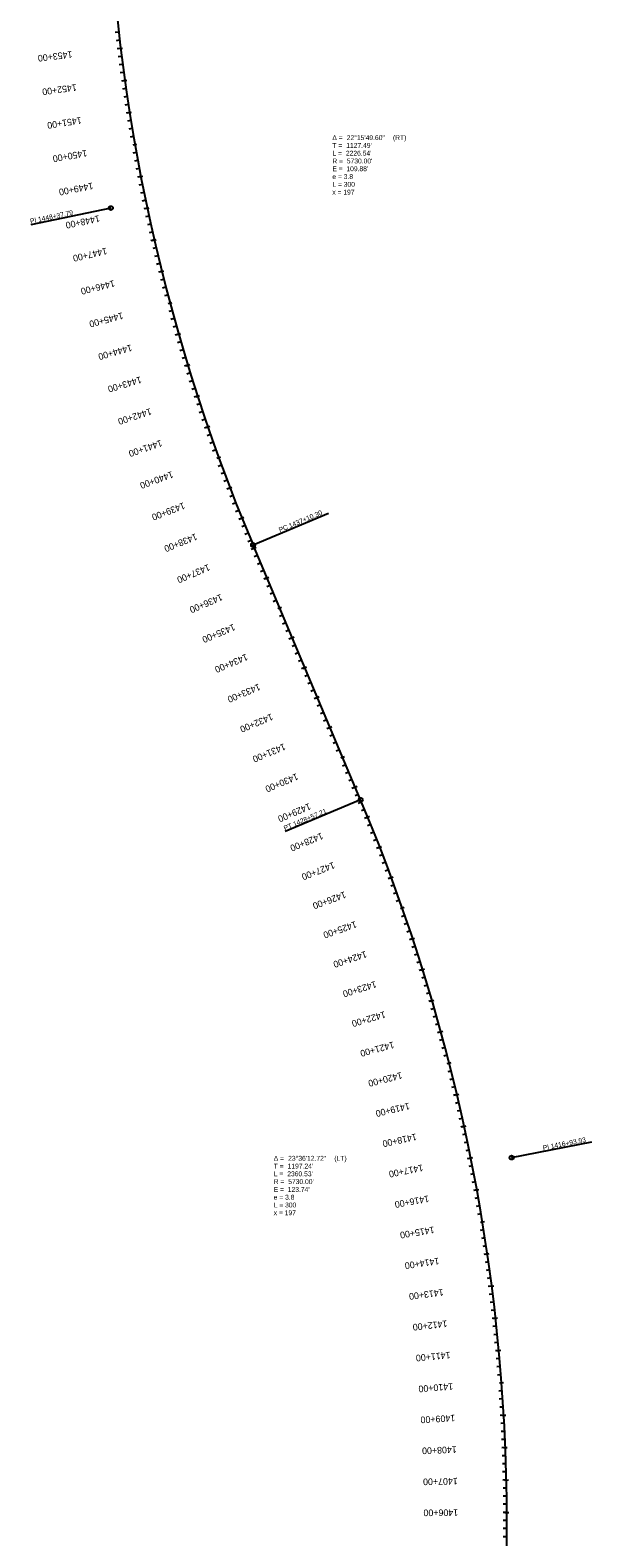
# Model space of a CAD drawing. Extents: x 20505176 to 20507193, y 7960287 to 7982631.
# Drawn here: x 20505239 to 20506971, y 7973323 to 7977971 of the extents above; entities that cross this region are included whole.
import ezdxf

# ---------------------------------------------------------------- set-up
doc = ezdxf.new("R2010")
doc.units = 0
for name, color, linetype in [('Alignment', 7, 'Continuous'), ('TextAlignment', 7, 'Continuous'), ('TextAlignmentLrg', 7, 'Continuous'), ('TextAlignmentSml', 7, 'Continuous')]:
    doc.layers.add(name, color=color, linetype=linetype)

msp = doc.modelspace()

# ---------------------------------------------------------------- linework, layer by layer
at = {"layer": 'Alignment'}
msp.add_line((20506257.8, 7975598.2), (20505926.1, 7976384.1), dxfattribs=at)
for centre, start, end in [((20511205.4, 7978611.7), 180.61343, 202.8772), ((20500978.6, 7973370.4), 359.27591, 22.87944)]:
    msp.add_arc(centre, 5730, start, end, dxfattribs=at)
at = {"layer": 'TextAlignment'}
for p, q in [((20505487.8, 7977422.9), (20505241.1, 7977371.6)), ((20505241.1, 7977371.6), (20505241.1, 7977371.6)), ((20505926.1, 7976384.1), (20506158.3, 7976482.1)), ((20506158.3, 7976482.1), (20506158.3, 7976482.1)), ((20506257.8, 7975598.2), (20506025.6, 7975500.2)), ((20506025.6, 7975500.2), (20506025.6, 7975500.2)), ((20506723.2, 7974495.1), (20506970.5, 7974543.5)), ((20506970.5, 7974543.5), (20506970.5, 7974543.5))]:
    msp.add_line(p, q, dxfattribs=at)
for centre in [(20505487.8, 7977422.9), (20505926.1, 7976384.1), (20506257.8, 7975598.2), (20506723.2, 7974495.1)]:
    msp.add_circle(centre, 6.24, dxfattribs=at)
at = {"layer": 'TextAlignmentLrg'}
for p, q in [((20505517.9, 7977915.3), (20505507, 7977913.9)), ((20505530.9, 7977816.1), (20505520.1, 7977814.6)), ((20505545.7, 7977717.2), (20505534.9, 7977715.5)), ((20505556.1, 7977617.5), (20505568.2, 7977619.6)), ((20505580.3, 7977520.2), (20505569.6, 7977518.2)), ((20505600.2, 7977422.2), (20505589.5, 7977420)), ((20505621.8, 7977324.6), (20505611.2, 7977322.2)), ((20505645.1, 7977227.4), (20505634.6, 7977224.7)), ((20505664.2, 7977129), (20505676.1, 7977132.1)), ((20505696.8, 7977034.2), (20505686.3, 7977031.2)), ((20505725.2, 7976938.3), (20505714.8, 7976935.1)), ((20505755.3, 7976842.9), (20505744.9, 7976839.5)), ((20505786.9, 7976748.1), (20505776.6, 7976744.5)), ((20505814.5, 7976651.7), (20505826, 7976655.9)), ((20505855.3, 7976560.1), (20505845.1, 7976556.2)), ((20505891.9, 7976467.1), (20505881.8, 7976463)), ((20505930.1, 7976374.7), (20505920.1, 7976370.4)), ((20505969, 7976282.5), (20505958.9, 7976278.3)), ((20506002.2, 7976188), (20506013.5, 7976192.8)), ((20506046.8, 7976098.2), (20506036.7, 7976094)), ((20506085.6, 7976006.1), (20506075.6, 7976001.9)), ((20506124.5, 7975914), (20506114.4, 7975909.7)), ((20506163.4, 7975821.8), (20506153.3, 7975817.6)), ((20506196.6, 7975727.3), (20506207.9, 7975732.1)), ((20506241.1, 7975637.6), (20506231.1, 7975633.3)), ((20506279.7, 7975545.3), (20506269.6, 7975541.2)), ((20506316.9, 7975452.5), (20506306.7, 7975448.5)), ((20506352.4, 7975359), (20506342.2, 7975355.2)), ((20506380.5, 7975262.9), (20506392.1, 7975267)), ((20506418.5, 7975170.3), (20506408.2, 7975166.8)), ((20506449.1, 7975075.1), (20506438.7, 7975071.8)), ((20506478, 7974979.3), (20506467.5, 7974976.3)), ((20506505.3, 7974883.1), (20506494.7, 7974880.2)), ((20506524.9, 7974784.9), (20506536.8, 7974788)), ((20506554.7, 7974689.3), (20506544.1, 7974686.8)), ((20506576.9, 7974591.8), (20506566.2, 7974589.5)), ((20506597.3, 7974493.9), (20506586.6, 7974491.8)), ((20506616.1, 7974395.7), (20506605.3, 7974393.8)), ((20506627.1, 7974296.2), (20506639.2, 7974298.2)), ((20506648.4, 7974198.4), (20506637.6, 7974196.8)), ((20506662, 7974099.3), (20506651.2, 7974097.9)), ((20506673.9, 7974000), (20506663, 7973998.8)), ((20506684, 7973900.5), (20506673.1, 7973899.5)), ((20506686.3, 7973800.4), (20506698.5, 7973801.3)), ((20506699, 7973701.1), (20506688.1, 7973700.5)), ((20506703.9, 7973601.2), (20506693, 7973600.8)), ((20506707.1, 7973501.3), (20506696.2, 7973501)), ((20506708.5, 7973401.3), (20506697.6, 7973401.2))]:
    msp.add_line(p, q, dxfattribs=at)
at = {"layer": 'TextAlignmentSml'}
for p, q in [((20505512, 7977964.9), (20505501.2, 7977963.7)), ((20505514.9, 7977940.1), (20505504.1, 7977938.8)), ((20505511.8, 7977914.5), (20505524, 7977916)), ((20505521, 7977890.4), (20505510.1, 7977889.1)), ((20505524.2, 7977865.7), (20505513.4, 7977864.2)), ((20505527.5, 7977840.9), (20505516.7, 7977839.4)), ((20505524.8, 7977815.3), (20505537, 7977817)), ((20505534.4, 7977791.4), (20505523.6, 7977789.8)), ((20505538.1, 7977766.6), (20505527.3, 7977765)), ((20505541.8, 7977741.9), (20505531, 7977740.2)), ((20505539.6, 7977716.2), (20505551.7, 7977718.2)), ((20505549.6, 7977692.5), (20505538.8, 7977690.8)), ((20505553.7, 7977667.9), (20505542.9, 7977666.1)), ((20505557.8, 7977643.2), (20505547.1, 7977641.4)), ((20505556.1, 7977617.5), (20505568.2, 7977619.6)), ((20505566.5, 7977594), (20505555.8, 7977592)), ((20505571, 7977569.4), (20505560.3, 7977567.4)), ((20505575.6, 7977544.8), (20505564.9, 7977542.8)), ((20505574.3, 7977519.1), (20505586.3, 7977521.4)), ((20505585.1, 7977495.7), (20505574.4, 7977493.6)), ((20505590.1, 7977471.2), (20505579.4, 7977469)), ((20505595.1, 7977446.7), (20505584.4, 7977444.5)), ((20505594.2, 7977421), (20505606.2, 7977423.5)), ((20505605.5, 7977397.8), (20505594.8, 7977395.5)), ((20505610.8, 7977373.4), (20505600.2, 7977371)), ((20505616.3, 7977349), (20505605.6, 7977346.6)), ((20505615.9, 7977323.2), (20505627.8, 7977326)), ((20505627.5, 7977300.3), (20505616.9, 7977297.8)), ((20505633.3, 7977275.9), (20505622.7, 7977273.4)), ((20505639.2, 7977251.6), (20505628.6, 7977249)), ((20505639.2, 7977225.9), (20505651.1, 7977228.8)), ((20505651.2, 7977203.1), (20505640.7, 7977200.4)), ((20505657.4, 7977178.9), (20505646.9, 7977176.2)), ((20505663.7, 7977154.7), (20505653.2, 7977151.9)), ((20505664.2, 7977129), (20505676.1, 7977132.1)), ((20505676.7, 7977106.4), (20505666.1, 7977103.5)), ((20505683.3, 7977082.3), (20505672.8, 7977079.4)), ((20505690, 7977058.2), (20505679.5, 7977055.3)), ((20505691, 7977032.5), (20505702.7, 7977035.9)), ((20505703.8, 7977010.2), (20505693.3, 7977007.1)), ((20505710.8, 7976986.2), (20505700.3, 7976983.1)), ((20505718, 7976962.2), (20505707.5, 7976959.1)), ((20505719.4, 7976936.5), (20505731.1, 7976940.1)), ((20505732.6, 7976914.4), (20505722.1, 7976911.2)), ((20505740, 7976890.5), (20505729.6, 7976887.2)), ((20505747.6, 7976866.7), (20505737.2, 7976863.4)), ((20505749.4, 7976841), (20505761.1, 7976844.8)), ((20505763, 7976819.1), (20505752.6, 7976815.7)), ((20505770.9, 7976795.4), (20505760.5, 7976791.9)), ((20505778.9, 7976771.7), (20505768.5, 7976768.2)), ((20505781.2, 7976746.1), (20505792.7, 7976750.1)), ((20505795.1, 7976724.4), (20505784.8, 7976720.8)), ((20505803.4, 7976700.8), (20505793.1, 7976697.2)), ((20505811.8, 7976677.3), (20505801.5, 7976673.6)), ((20505814.5, 7976651.7), (20505826, 7976655.9)), ((20505828.9, 7976630.3), (20505818.6, 7976626.5)), ((20505837.6, 7976606.9), (20505827.4, 7976603)), ((20505846.4, 7976583.5), (20505836.2, 7976579.6)), ((20505849.6, 7976557.9), (20505861, 7976562.3)), ((20505864.3, 7976536.8), (20505854.1, 7976532.8)), ((20505873.4, 7976513.5), (20505863.2, 7976509.5)), ((20505882.6, 7976490.3), (20505872.5, 7976486.2)), ((20505886.2, 7976464.8), (20505897.6, 7976469.3)), ((20505901.3, 7976443.9), (20505891.2, 7976439.8)), ((20505910.8, 7976420.8), (20505900.7, 7976416.6)), ((20505920.4, 7976397.7), (20505910.4, 7976393.5)), ((20505924.5, 7976372.3), (20505935.8, 7976377)), ((20505939.8, 7976351.6), (20505929.8, 7976347.4)), ((20505949.6, 7976328.6), (20505939.5, 7976324.3)), ((20505959.3, 7976305.5), (20505949.2, 7976301.3)), ((20505963.4, 7976280.1), (20505974.6, 7976284.9)), ((20505978.7, 7976259.5), (20505968.7, 7976255.2)), ((20505988.4, 7976236.4), (20505978.4, 7976232.2)), ((20505998.2, 7976213.4), (20505988.1, 7976209.2)), ((20506002.2, 7976188), (20506013.5, 7976192.8)), ((20506017.6, 7976167.3), (20506007.5, 7976163.1)), ((20506027.3, 7976144.3), (20506017.3, 7976140.1)), ((20506037, 7976121.3), (20506027, 7976117)), ((20506041.1, 7976095.9), (20506052.4, 7976100.6)), ((20506056.5, 7976075.2), (20506046.4, 7976071)), ((20506066.2, 7976052.2), (20506056.1, 7976047.9)), ((20506075.9, 7976029.1), (20506065.8, 7976024.9)), ((20506080, 7976003.7), (20506091.3, 7976008.5)), ((20506095.3, 7975983.1), (20506085.3, 7975978.8)), ((20506105.1, 7975960), (20506095, 7975955.8)), ((20506114.8, 7975937), (20506104.7, 7975932.8)), ((20506118.9, 7975911.6), (20506130.1, 7975916.4)), ((20506134.2, 7975890.9), (20506124.2, 7975886.7)), ((20506143.9, 7975867.9), (20506133.9, 7975863.7)), ((20506153.7, 7975844.9), (20506143.6, 7975840.6)), ((20506157.7, 7975819.5), (20506169, 7975824.2)), ((20506173.1, 7975798.8), (20506163, 7975794.6)), ((20506182.8, 7975775.8), (20506172.8, 7975771.5)), ((20506192.5, 7975752.7), (20506182.5, 7975748.5)), ((20506196.6, 7975727.3), (20506207.9, 7975732.1)), ((20506212, 7975706.7), (20506201.9, 7975702.4)), ((20506221.7, 7975683.6), (20506211.6, 7975679.4)), ((20506231.4, 7975660.6), (20506221.3, 7975656.4)), ((20506235.5, 7975635.2), (20506246.8, 7975640)), ((20506250.8, 7975614.5), (20506240.8, 7975610.3)), ((20506260.6, 7975591.5), (20506250.5, 7975587.3)), ((20506270.2, 7975568.4), (20506260.1, 7975564.2)), ((20506274.1, 7975543), (20506285.4, 7975547.7)), ((20506289.2, 7975522.2), (20506279.1, 7975518.1)), ((20506298.5, 7975499), (20506288.4, 7975494.9)), ((20506307.8, 7975475.8), (20506297.6, 7975471.7)), ((20506311.2, 7975450.3), (20506322.6, 7975454.7)), ((20506325.9, 7975429.2), (20506315.7, 7975425.3)), ((20506334.9, 7975405.8), (20506324.6, 7975401.9)), ((20506343.7, 7975382.4), (20506333.5, 7975378.6)), ((20506346.7, 7975356.9), (20506358.1, 7975361.1)), ((20506361, 7975335.5), (20506350.8, 7975331.8)), ((20506369.6, 7975312), (20506359.3, 7975308.3)), ((20506378, 7975288.5), (20506367.7, 7975284.8)), ((20506380.5, 7975262.9), (20506392.1, 7975267)), ((20506394.5, 7975241.3), (20506384.2, 7975237.8)), ((20506402.6, 7975217.7), (20506392.3, 7975214.1)), ((20506410.6, 7975194), (20506400.3, 7975190.5)), ((20506412.7, 7975168.3), (20506424.3, 7975172.2)), ((20506426.3, 7975146.5), (20506416, 7975143.1)), ((20506434, 7975122.7), (20506423.6, 7975119.4)), ((20506441.6, 7975098.9), (20506431.2, 7975095.6)), ((20506443.3, 7975073.2), (20506455, 7975076.9)), ((20506456.5, 7975051.2), (20506446.1, 7975048)), ((20506463.8, 7975027.3), (20506453.3, 7975024.1)), ((20506471, 7975003.3), (20506460.5, 7975000.2)), ((20506472.2, 7974977.6), (20506483.9, 7974981.1)), ((20506485, 7974955.3), (20506474.5, 7974952.3)), ((20506491.9, 7974931.3), (20506481.4, 7974928.3)), ((20506498.6, 7974907.2), (20506488.1, 7974904.3)), ((20506499.4, 7974881.5), (20506511.2, 7974884.7)), ((20506511.8, 7974859), (20506501.3, 7974856.2)), ((20506518.3, 7974834.8), (20506507.7, 7974832)), ((20506524.6, 7974810.7), (20506514, 7974807.9)), ((20506524.9, 7974784.9), (20506536.8, 7974788)), ((20506537, 7974762.2), (20506526.4, 7974759.5)), ((20506543, 7974737.9), (20506532.4, 7974735.3)), ((20506548.9, 7974713.6), (20506538.3, 7974711.1)), ((20506548.7, 7974687.9), (20506560.7, 7974690.7)), ((20506560.4, 7974665), (20506549.8, 7974662.5)), ((20506566, 7974640.6), (20506555.3, 7974638.2)), ((20506571.5, 7974616.2), (20506560.8, 7974613.9)), ((20506570.9, 7974590.5), (20506582.8, 7974593.1)), ((20506582.1, 7974567.4), (20506571.5, 7974565.1)), ((20506587.3, 7974542.9), (20506576.6, 7974540.7)), ((20506592.4, 7974518.4), (20506581.7, 7974516.3)), ((20506591.3, 7974492.7), (20506603.3, 7974495.1)), ((20506602.2, 7974469.4), (20506591.5, 7974467.3)), ((20506606.9, 7974444.9), (20506596.2, 7974442.8)), ((20506611.6, 7974420.3), (20506600.8, 7974418.3)), ((20506620.5, 7974371.1), (20506609.7, 7974369.2)), ((20506610.1, 7974394.6), (20506622.1, 7974396.8)), ((20506624.8, 7974346.5), (20506614, 7974344.6)), ((20506629, 7974321.8), (20506618.2, 7974320)), ((20506637.1, 7974272.5), (20506626.3, 7974270.8)), ((20506627.1, 7974296.2), (20506639.2, 7974298.2)), ((20506641, 7974247.8), (20506630.2, 7974246.1)), ((20506644.8, 7974223.1), (20506634, 7974221.5)), ((20506642.4, 7974197.5), (20506654.5, 7974199.2)), ((20506652, 7974173.6), (20506641.2, 7974172.1)), ((20506655.4, 7974148.9), (20506644.6, 7974147.4)), ((20506658.8, 7974124.1), (20506648, 7974122.6)), ((20506655.9, 7974098.5), (20506668.1, 7974100.1)), ((20506665.1, 7974074.5), (20506654.3, 7974073.1)), ((20506668.2, 7974049.7), (20506657.3, 7974048.4)), ((20506671.1, 7974024.8), (20506660.2, 7974023.6)), ((20506667.8, 7973999.3), (20506679.9, 7974000.7)), ((20506676.6, 7973975.1), (20506665.7, 7973974)), ((20506679.1, 7973950.3), (20506668.3, 7973949.2)), ((20506681.6, 7973925.4), (20506670.8, 7973924.3)), ((20506677.9, 7973899.9), (20506690.1, 7973901.1)), ((20506686.2, 7973875.6), (20506675.4, 7973874.6)), ((20506688.4, 7973850.7), (20506677.5, 7973849.8)), ((20506690.4, 7973825.8), (20506679.6, 7973824.9)), ((20506694.2, 7973775.9), (20506683.3, 7973775.2)), ((20506686.3, 7973800.4), (20506698.5, 7973801.3)), ((20506695.9, 7973751), (20506685, 7973750.3)), ((20506697.5, 7973726), (20506686.6, 7973725.4)), ((20506700.4, 7973676.1), (20506689.5, 7973675.5)), ((20506692.9, 7973700.7), (20506705.1, 7973701.4)), ((20506701.7, 7973651.2), (20506690.8, 7973650.6)), ((20506702.9, 7973626.2), (20506691.9, 7973625.7)), ((20506704.9, 7973576.2), (20506694, 7973575.8)), ((20506697.8, 7973601), (20506710, 7973601.4)), ((20506705.7, 7973551.2), (20506694.8, 7973550.9)), ((20506706.4, 7973526.2), (20506695.5, 7973525.9)), ((20506701, 7973501.1), (20506713.2, 7973501.4)), ((20506707.6, 7973476.3), (20506696.7, 7973476.1)), ((20506708, 7973451.3), (20506697.1, 7973451.1)), ((20506708.3, 7973426.3), (20506697.4, 7973426.2)), ((20506702.4, 7973401.2), (20506714.6, 7973401.3)), ((20506708.6, 7973376.3), (20506697.6, 7973376.3)), ((20506708.5, 7973351.3), (20506697.6, 7973351.3)), ((20506708.4, 7973326.3), (20506697.5, 7973326.3))]:
    msp.add_line(p, q, dxfattribs=at)

# ---------------------------------------------------------------- texts
at = {"layer": 'TextAlignment'}
for s, p in [('T = ', (20506170.5, 7977608.5)), ('Δ = ', (20506170.5, 7977632.5)), ("1127.49'", (20506213.4, 7977608.5)), ('22°15\'49.60"', (20506214.9, 7977632.5)), (' (RT)', (20506351.6, 7977632.5)), ('L = ', (20506170.5, 7977584.5)), ('R = ', (20506170.5, 7977560.5)), ("2226.54'", (20506212.3, 7977584.5)), ("5730.00'", (20506215.1, 7977560.5)), ('e = 3.8', (20506170.5, 7977512.5)), ('E = ', (20506170.5, 7977536.5)), ("109.88'", (20506213.8, 7977536.5)), ('x = 197', (20506170.5, 7977464.5)), ('L = 300', (20506170.5, 7977488.5)), ('T = ', (20505989.8, 7974461.6)), ('Δ = ', (20505989.8, 7974485.6)), ("1197.24'", (20506032.7, 7974461.6)), ('23°36\'12.72"', (20506034.3, 7974485.6)), (' (LT)', (20506171, 7974485.6)), ('L = ', (20505989.8, 7974437.6)), ('R = ', (20505989.8, 7974413.6)), ("2360.53'", (20506031.6, 7974437.6)), ("5730.00'", (20506034.5, 7974413.6)), ('e = 3.8', (20505989.8, 7974365.6)), ('E = ', (20505989.8, 7974389.6)), ("123.74'", (20506033.2, 7974389.6)), ('x = 197', (20505989.8, 7974317.6)), ('L = 300', (20505989.8, 7974341.6))]:
    msp.add_text(s, height=15, dxfattribs=at).set_placement(p)
for s, rotation, p in [('PI ', 11.7453, (20505240.4, 7977374.9)), ('1448+37.79', 11.7453, (20505264.9, 7977380)), ('1437+10.30', 22.8772, (20506039.9, 7976435.7)), ('PC', 22.8772, (20506009.2, 7976422.8)), ('PT', 22.8794, (20506024.3, 7975503.2)), ('1428+57.21', 22.8794, (20506053.3, 7975515.5)), ('1416+93.93', 11.0777, (20506845.4, 7974522.4)), ('PI ', 11.0777, (20506820.8, 7974517.6))]:
    msp.add_text(s, height=15, rotation=rotation, dxfattribs=at).set_placement(p)
at = {"layer": 'TextAlignmentLrg'}
for s, rotation, p in [('1450+00', 189.9811, (20505412.6, 7977602.6)), ('1445+00', 194.9808, (20505522.6, 7977101.6)), ('1440+00', 199.9804, (20505675.8, 7976612.1)), ('1435+00', 202.8763, (20505865.7, 7976141.5)), ('1430+00', 202.8763, (20506060.1, 7975680.8)), ('1425+00', 199.3076, (20506241.4, 7975225)), ('1420+00', 194.3079, (20506383, 7974759.3)), ('1415+00', 189.3083, (20506483.4, 7974283)), ('1410+00', 184.3087, (20506542, 7973799.8))]:
    msp.add_text(s, height=20.4, rotation=rotation, dxfattribs=at).set_placement(p)
at = {"layer": 'TextAlignmentSml'}
for s, rotation, p in [('1453+00', 186.9814, (20505367.8, 7977907.2)), ('1452+00', 187.9813, (20505380.9, 7977805.4)), ('1451+00', 188.9812, (20505395.9, 7977703.9)), ('1450+00', 189.9811, (20505412.6, 7977602.6)), ('1449+00', 190.9811, (20505431.1, 7977501.7)), ('1448+00', 191.981, (20505451.4, 7977401.1)), ('1447+00', 192.9809, (20505473.4, 7977300.9)), ('1446+00', 193.9808, (20505497.1, 7977201)), ('1445+00', 194.9808, (20505522.6, 7977101.6)), ('1444+00', 195.9807, (20505549.8, 7977002.7)), ('1443+00', 196.9806, (20505578.8, 7976904.2)), ('1442+00', 197.9806, (20505609.4, 7976806.3)), ('1441+00', 198.9805, (20505641.8, 7976708.9)), ('1440+00', 199.9804, (20505675.8, 7976612.1)), ('1439+00', 200.9803, (20505711.6, 7976515.9)), ('1438+00', 201.9803, (20505749, 7976420.4)), ('1437+00', 202.8763, (20505788, 7976325.7)), ('1436+00', 202.8763, (20505826.8, 7976233.6)), ('1435+00', 202.8763, (20505865.7, 7976141.5)), ('1434+00', 202.8763, (20505904.6, 7976049.3)), ('1433+00', 202.8763, (20505943.5, 7975957.2)), ('1432+00', 202.8763, (20505982.3, 7975865.1)), ('1431+00', 202.8763, (20506021.2, 7975772.9)), ('1430+00', 202.8763, (20506060.1, 7975680.8)), ('1429+00', 202.8763, (20506099, 7975588.7)), ('1428+00', 202.3073, (20506137.1, 7975497.8)), ('1427+00', 201.3074, (20506173.4, 7975407.5)), ('1426+00', 200.3075, (20506208.2, 7975316.5)), ('1425+00', 199.3076, (20506241.4, 7975225)), ('1424+00', 198.3076, (20506272.9, 7975132.8)), ('1423+00', 197.3077, (20506302.9, 7975040.2)), ('1422+00', 196.3078, (20506331.2, 7974947)), ('1421+00', 195.3078, (20506357.9, 7974853.4)), ('1420+00', 194.3079, (20506383, 7974759.3)), ('1419+00', 193.308, (20506406.4, 7974664.7)), ('1418+00', 192.3081, (20506428.1, 7974569.8)), ('1417+00', 191.3081, (20506448.2, 7974474.5)), ('1416+00', 190.3082, (20506466.7, 7974378.9)), ('1415+00', 189.3083, (20506483.4, 7974283)), ('1414+00', 188.3084, (20506498.5, 7974186.8)), ('1413+00', 187.3084, (20506511.9, 7974090.3)), ('1412+00', 186.3085, (20506523.7, 7973993.6)), ('1411+00', 185.3086, (20506533.7, 7973896.8)), ('1410+00', 184.3087, (20506542, 7973799.8)), ('1409+00', 183.3087, (20506548.7, 7973702.6)), ('1408+00', 182.3088, (20506553.6, 7973605.4)), ('1407+00', 181.3089, (20506556.9, 7973508)), ('1406+00', 180.309, (20506558.4, 7973410.7))]:
    msp.add_text(s, height=20.4, rotation=rotation, dxfattribs=at).set_placement(p)

doc.saveas('drawing.dxf')
